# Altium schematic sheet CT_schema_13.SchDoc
size 387 x 278 mm
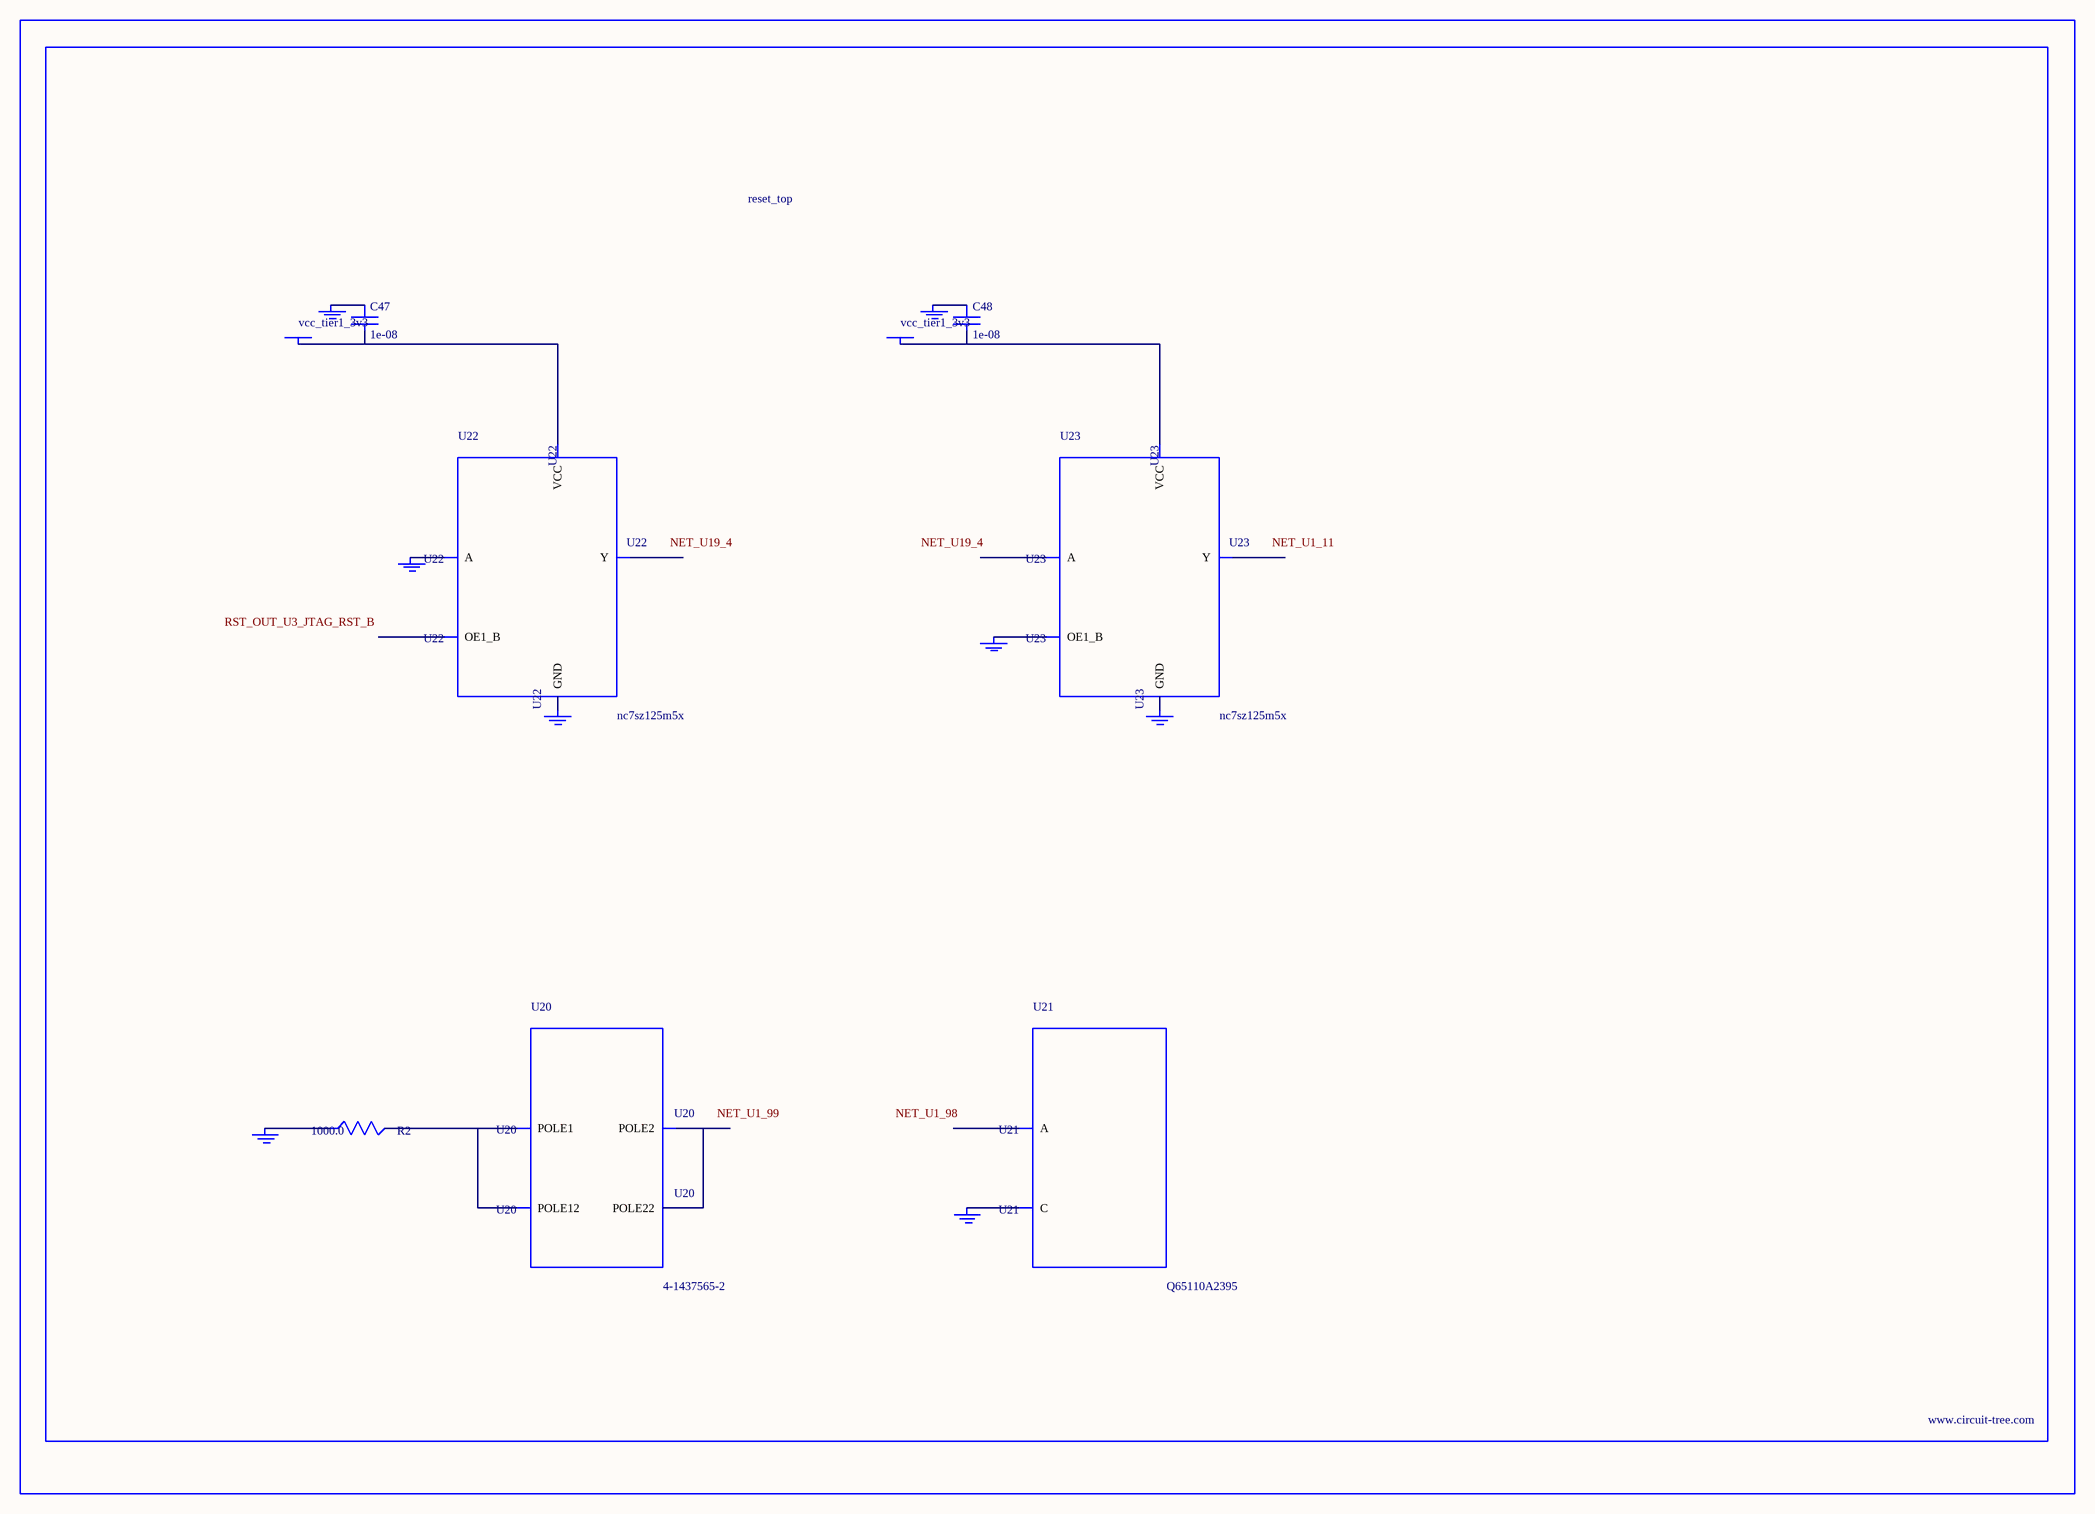
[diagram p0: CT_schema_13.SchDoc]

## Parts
BORDER12  (no value)
C47  1e-08  [C0402]
C48  1e-08  [C0402]
GND_INSTANCE_12_0  (no value)
GND_INSTANCE_12_1  (no value)
GND_INSTANCE_12_2  (no value)
GND_INSTANCE_12_3  (no value)
GND_INSTANCE_12_4  (no value)
GND_INSTANCE_12_5  (no value)
GND_INSTANCE_12_6  (no value)
GND_INSTANCE_12_7  (no value)
POWER_INSTANCE_12_0  vcc_tier1_3v3
POWER_INSTANCE_12_1  vcc_tier1_3v3
R2  1000.0  [R0603]
U20  4-1437565-2  [SW_4-1437565-2]
U21  Q65110A2395  [LGM67K-G1J2-24-Z]
U22  nc7sz125m5x  [NC7SZ125M5X]
U23  nc7sz125m5x  [NC7SZ125M5X]

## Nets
NetC47_1: C47.1 GND_INSTANCE_12_2.0(GND)
NetC47_2: C47.2 POWER_INSTANCE_12_0.0(PWR) U22.5(VCC)
NetC48_1: C48.1 GND_INSTANCE_12_5.0(GND)
NetC48_2: C48.2 POWER_INSTANCE_12_1.0(PWR) U23.5(VCC)
NetGND_INSTANCE_12_0_0: GND_INSTANCE_12_0.0(GND) R2.1
NetGND_INSTANCE_12_1_0: GND_INSTANCE_12_1.0(GND) U21.C
NetGND_INSTANCE_12_3_0: GND_INSTANCE_12_3.0(GND) U22.2(A)
NetGND_INSTANCE_12_4_0: GND_INSTANCE_12_4.0(GND) U22.3(GND)
NetGND_INSTANCE_12_6_0: GND_INSTANCE_12_6.0(GND) U23.1(OE1_B)
NetGND_INSTANCE_12_7_0: GND_INSTANCE_12_7.0(GND) U23.3(GND)
NetR2_2: R2.2 U20.1(POLE1) U20.2(POLE12)
NetU20_3: U20.3(POLE2) U20.4(POLE22)

Not connected (* = marked no-connect by the designer): U21 A; U22 1(OE1_B) 4(Y); U23 2(A) 4(Y)

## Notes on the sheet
- Labels drawn without touching a wire or pin: NET_U1_11, NET_U1_98, NET_U1_99, NET_U19_4, RST_OUT_U3_JTAG_RST_B

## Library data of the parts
BORDER12 = BORDER_PAGE12
C47 C48 = C0402C103K3RAC
GND_INSTANCE_12_0-GND_INSTANCE_12_7 = GND
POWER_INSTANCE_12_0 POWER_INSTANCE_12_1 = PWR
R2 = RC0603JR-071KL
